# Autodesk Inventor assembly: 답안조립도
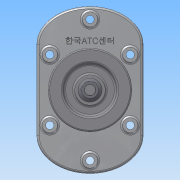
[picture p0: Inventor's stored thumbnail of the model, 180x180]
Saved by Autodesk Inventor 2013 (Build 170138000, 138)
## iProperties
Created: 2015-02
Part Number: 답안조립도
Document SubType Name: Assembly
Designer: Administrator
Author: Administrator
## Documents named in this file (12)
- C:\Users\Administrator\Desktop\450208V1019\답안조립도.iam
- C:\Users\Administrator\Desktop\450208V1019\본체.ipt
- C:\Users\Administrator\Desktop\450208V1019\2-커버.ipt
- C:\Users\Administrator\Desktop\450208V1019\3-축.ipt
- C:\Users\Administrator\Desktop\450208V1019\4-V벨트풀리.ipt
- C:\Users\Administrator\Desktop\450208V1019\5-체인 스프로킷.ipt
- C:\Users\Administrator\Desktop\450208V1019\6-베어링 6206.ipt
- C:\Users\Administrator\Desktop\450208V1019\7-부시.ipt
- C:\Users\Administrator\Desktop\450208V1019\8-오일실 30x42.ipt
- C:\Users\Administrator\Desktop\450208V1019\9-M16-너트.ipt
- C:\Users\Administrator\Desktop\450208V1019\10-M6.ipt
- C:\Users\Administrator\Desktop\450208V1019\11-키 6x6.ipt
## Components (21 placed, 10 different names)
1. 2-커버:1
2. 3-축:1
3. 4-V벨트풀리:1
4. 5-체인 스프로킷:1
5. 6-베어링 6206:1
6. 7-부시:1
7. 9-M16 너트:1
8. 11-키 6x6:1
9. 11-키 6x6:2
10. 6-베어링 6206:2
11. 2-커버:2
12. 8-8-오일실 30x42:2
13. 9-M16 너트:2
14. 10-M6:2
15. 10-M6:3
16. 10-M6:4
17. 10-M6:5
18. 10-M6:1
19. 10-M6:6
20. 10-M6:7
21. 10-M6:8
